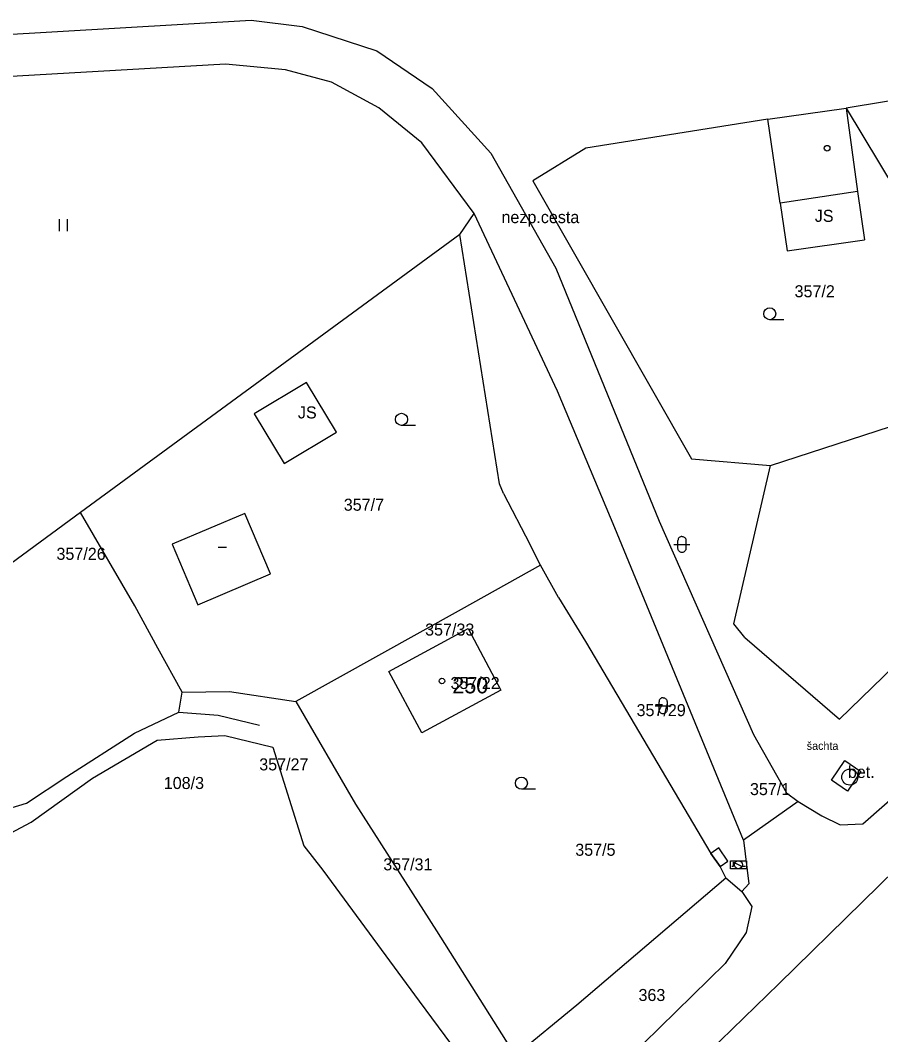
# Model space of a CAD drawing. Extents: x -836739 to -835945, y -1070775 to -1070126.
# Drawn here: x -836511.6 to -836458, y -1070275.3 to -1070212.1 of the extents above; entities that cross this region are included whole.
import ezdxf

# ---------------------------------------------------------------- set-up
doc = ezdxf.new("R2010")
doc.units = 0
for name, color, linetype in [('BodPole_mer', 7, 'Continuous'), ('Budovy_hranice', 7, 'Continuous'), ('Budovy_kody', 7, 'Continuous'), ('Doprava_hranice', 7, 'Continuous'), ('Doprava_kody', 7, 'Continuous'), ('OstPloch_hranice', 7, 'Continuous'), ('OstPloch_kody', 7, 'Continuous'), ('PovrZnIS_body', 7, 'Continuous'), ('PovrZnIS_hranice', 7, 'Continuous'), ('RuianAdr_popis', 7, 'Continuous'), ('RuianPar_popis', 7, 'Continuous'), ('Stavby_hr_stav', 7, 'Continuous'), ('Stavby_kody', 7, 'Continuous'), ('Stavby_linie', 7, 'Continuous'), ('Stavby_popis', 7, 'Continuous'), ('Vodstvo_hranice', 7, 'Continuous')]:
    doc.layers.add(name, color=color, linetype=linetype)

msp = doc.modelspace()

# ---------------------------------------------------------------- linework, layer by layer
at = {"layer": 'BodPole_mer'}
for p, q in [((-836497.22, -1070212.11), (-836497.22, -1070212.11)), ((-836494.05, -1070212.5), (-836494.05, -1070212.5)), ((-836489.39, -1070214.02), (-836489.39, -1070214.02)), ((-836498.82, -1070214.84), (-836498.82, -1070214.84)), ((-836495.08, -1070215.2), (-836495.08, -1070215.2)), ((-836492.22, -1070215.97), (-836492.22, -1070215.97)), ((-836485.93, -1070216.36), (-836485.93, -1070216.36)), ((-836489.27, -1070217.57), (-836489.27, -1070217.57)), ((-836460.13, -1070217.59), (-836460.13, -1070217.59)), ((-836465.02, -1070218.27), (-836465.02, -1070218.27)), ((-836486.58, -1070219.75), (-836486.58, -1070219.75)), ((-836482.28, -1070220.4), (-836482.28, -1070220.4)), ((-836476.36, -1070220.08), (-836476.36, -1070220.08)), ((-836479.66, -1070222.11), (-836479.66, -1070222.11)), ((-836459.42, -1070222.78), (-836459.42, -1070222.78)), ((-836464.25, -1070223.5), (-836464.25, -1070223.5)), ((-836483.33, -1070224.14), (-836483.33, -1070224.14)), ((-836484.22, -1070225.45), (-836484.22, -1070225.45)), ((-836459, -1070225.8), (-836459, -1070225.8)), ((-836463.81, -1070226.48), (-836463.81, -1070226.48)), ((-836478.23, -1070227.56), (-836478.23, -1070227.56)), ((-836493.77, -1070234.68), (-836493.77, -1070234.68)), ((-836478.12, -1070235.21), (-836478.12, -1070235.21)), ((-836497.03, -1070236.63), (-836497.03, -1070236.63)), ((-836491.91, -1070237.78), (-836491.91, -1070237.78)), ((-836469.78, -1070239.43), (-836469.78, -1070239.43)), ((-836495.17, -1070239.73), (-836495.17, -1070239.73)), ((-836464.85, -1070239.86), (-836464.85, -1070239.86)), ((-836481.74, -1070241), (-836481.74, -1070241)), ((-836481.49, -1070241.59), (-836481.49, -1070241.59)), ((-836507.86, -1070242.77), (-836507.86, -1070242.77)), ((-836497.61, -1070242.84), (-836497.61, -1070242.84)), ((-836474.56, -1070243.73), (-836474.56, -1070243.73)), ((-836471.79, -1070243.33), (-836471.79, -1070243.33)), ((-836502.15, -1070244.76), (-836502.15, -1070244.76)), ((-836479.85, -1070244.75), (-836479.85, -1070244.75)), ((-836479.18, -1070246.06), (-836479.18, -1070246.06)), ((-836496.01, -1070246.6), (-836496.01, -1070246.6)), ((-836478.06, -1070248.07), (-836478.06, -1070248.07)), ((-836504.47, -1070248.59), (-836504.47, -1070248.59)), ((-836500.55, -1070248.53), (-836500.55, -1070248.53)), ((-836484.13, -1070248.82), (-836484.13, -1070248.82)), ((-836483.69, -1070250.01), (-836483.69, -1070250.01)), ((-836467.14, -1070249.72), (-836467.14, -1070249.72)), ((-836476.39, -1070250.81), (-836476.39, -1070250.81)), ((-836466.44, -1070250.56), (-836466.44, -1070250.56)), ((-836503.04, -1070251.23), (-836503.04, -1070251.23)), ((-836488.64, -1070252.68), (-836488.64, -1070252.68)), ((-836501.52, -1070253.97), (-836501.52, -1070253.97)), ((-836498.58, -1070253.94), (-836498.58, -1070253.94)), ((-836481.66, -1070253.86), (-836481.66, -1070253.86)), ((-836494.44, -1070254.55), (-836494.44, -1070254.55)), ((-836501.74, -1070255.22), (-836501.74, -1070255.22)), ((-836499.27, -1070255.4), (-836499.27, -1070255.4)), ((-836460.54, -1070255.66), (-836460.54, -1070255.66)), ((-836504.49, -1070256.53), (-836504.49, -1070256.53)), ((-836496.7, -1070256.04), (-836496.7, -1070256.04)), ((-836486.58, -1070256.5), (-836486.58, -1070256.5)), ((-836503.08, -1070256.96), (-836503.08, -1070256.96)), ((-836500.52, -1070256.76), (-836500.52, -1070256.76)), ((-836498.86, -1070256.68), (-836498.86, -1070256.68)), ((-836465.92, -1070256.62), (-836465.92, -1070256.62)), ((-836495.87, -1070257.41), (-836495.87, -1070257.41)), ((-836460.21, -1070258.24), (-836460.21, -1070258.24)), ((-836459.22, -1070258.92), (-836459.22, -1070258.92)), ((-836508.71, -1070259.23), (-836508.71, -1070259.23)), ((-836507.11, -1070259.33), (-836507.11, -1070259.33)), ((-836461.05, -1070259.46), (-836461.05, -1070259.46)), ((-836459.91, -1070259.27), (-836459.91, -1070259.27)), ((-836463.85, -1070260.25), (-836463.85, -1070260.25)), ((-836460.06, -1070260.14), (-836460.06, -1070260.14)), ((-836511.22, -1070260.9), (-836511.22, -1070260.9)), ((-836490.71, -1070260.96), (-836490.71, -1070260.96)), ((-836463.13, -1070260.78), (-836463.13, -1070260.78)), ((-836510.93, -1070262.08), (-836510.93, -1070262.08)), ((-836461.66, -1070261.68), (-836461.66, -1070261.68)), ((-836459.09, -1070262.17), (-836459.09, -1070262.17)), ((-836460.5, -1070262.24), (-836460.5, -1070262.24)), ((-836466.54, -1070263.19), (-836466.54, -1070263.19)), ((-836493.93, -1070263.56), (-836493.93, -1070263.56)), ((-836468.56, -1070264.02), (-836468.56, -1070264.02)), ((-836468.07, -1070263.68), (-836468.07, -1070263.68)), ((-836467.5, -1070264.5), (-836467.5, -1070264.5)), ((-836466.85, -1070264.73), (-836466.85, -1070264.73)), ((-836492.75, -1070265.06), (-836492.75, -1070265.06)), ((-836467.99, -1070264.84), (-836467.99, -1070264.84)), ((-836467.63, -1070265.54), (-836467.63, -1070265.54)), ((-836466.2, -1070265.91), (-836466.2, -1070265.91)), ((-836466.63, -1070266.39), (-836466.63, -1070266.39)), ((-836466.02, -1070267.34), (-836466.02, -1070267.34)), ((-836485.67, -1070268.85), (-836485.67, -1070268.85)), ((-836466.37, -1070268.96), (-836466.37, -1070268.96)), ((-836467.68, -1070270.88), (-836467.68, -1070270.88)), ((-836464.34, -1070272.16), (-836464.34, -1070272.16)), ((-836486.76, -1070273.24), (-836486.76, -1070273.24)), ((-836476.92, -1070273.45), (-836476.92, -1070273.45))]:
    msp.add_line(p, q, dxfattribs=at)
at = {"layer": 'Budovy_hranice'}
for p, q in [((-836497.61, -1070242.84), (-836502.15, -1070244.76)), ((-836496.01, -1070246.6), (-836497.61, -1070242.84)), ((-836502.15, -1070244.76), (-836500.55, -1070248.53)), ((-836500.55, -1070248.53), (-836496.01, -1070246.6))]:
    msp.add_line(p, q, dxfattribs=at)
for points in [[(-836460.13, -1070217.59), (-836459.42, -1070222.78), (-836464.25, -1070223.5), (-836465.02, -1070218.27), (-836460.13, -1070217.59)], [(-836481.66, -1070253.86), (-836486.58, -1070256.5), (-836488.64, -1070252.68), (-836483.69, -1070250.01), (-836481.66, -1070253.86)]]:
    msp.add_lwpolyline(points, dxfattribs=at)
at = {"layer": 'Budovy_kody'}
msp.add_line((-836499.27, -1070244.94), (-836498.77, -1070244.94), dxfattribs=at)
for centre in [(-836461.32, -1070220.08), (-836485.33, -1070253.28)]:
    msp.add_circle(centre, 0.175, dxfattribs=at)
at = {"layer": 'Doprava_hranice'}
for points in [[(-836565.55, -1070255.75), (-836568.29, -1070246.94), (-836565.3, -1070243.45), (-836558.59, -1070239.29), (-836553.32, -1070234.26), (-836550.36, -1070230.73), (-836544.63, -1070222.38), (-836541.42, -1070218.21), (-836539.02, -1070215.95), (-836535.5, -1070213.99), (-836517.48, -1070213.29), (-836497.22, -1070212.11), (-836494.05, -1070212.5), (-836489.39, -1070214.02), (-836485.93, -1070216.36), (-836482.28, -1070220.4), (-836478.23, -1070227.56), (-836471.79, -1070243.33), (-836465.92, -1070256.62), (-836463.85, -1070260.25), (-836463.13, -1070260.78)], [(-836466.54, -1070263.19), (-836474.56, -1070243.73), (-836478.12, -1070235.21), (-836483.33, -1070224.14), (-836486.58, -1070219.75), (-836489.27, -1070217.57), (-836492.22, -1070215.97), (-836495.08, -1070215.2), (-836498.82, -1070214.84), (-836513.64, -1070215.7), (-836532.05, -1070216.8), (-836534.5, -1070217.36), (-836537.57, -1070219.18), (-836540.24, -1070221.43), (-836545, -1070227.8), (-836549.52, -1070233.43), (-836552.32, -1070236.92), (-836557.98, -1070243.27), (-836562.8, -1070249.08), (-836563.01, -1070249.54), (-836561.48, -1070254.69), (-836565.55, -1070255.75)], [(-836463.13, -1070260.78), (-836461.66, -1070261.68), (-836460.5, -1070262.24), (-836459.09, -1070262.17), (-836456.22, -1070259.67), (-836453.89, -1070261.93), (-836464.34, -1070272.16), (-836473.79, -1070281.33)], [(-836463.13, -1070260.78), (-836466.54, -1070263.19), (-836466.2, -1070265.91), (-836466.63, -1070266.39), (-836466.02, -1070267.34), (-836466.37, -1070268.96), (-836467.68, -1070270.88), (-836477.85, -1070280.85), (-836486.39, -1070290.44)]]:
    msp.add_lwpolyline(points, dxfattribs=at)
at = {"layer": 'OstPloch_hranice'}
for p, q in [((-836484.22, -1070225.45), (-836483.33, -1070224.14)), ((-836467.63, -1070265.54), (-836466.63, -1070266.39))]:
    msp.add_line(p, q, dxfattribs=at)
msp.add_lwpolyline([(-836459.22, -1070258.92), (-836460.06, -1070260.14), (-836461.05, -1070259.46), (-836460.21, -1070258.24), (-836459.22, -1070258.92)], dxfattribs=at)
at = {"layer": 'OstPloch_kody'}
for p, q in [((-836509.185, -1070224.51), (-836509.185, -1070225.26)), ((-836508.675, -1070225.26), (-836508.675, -1070224.51)), ((-836464.025, -1070230.77), (-836464.9, -1070230.77)), ((-836486.975, -1070237.35), (-836487.85, -1070237.35)), ((-836470.62, -1070245.02), (-836470.62, -1070244.52)), ((-836470.12, -1070244.52), (-836470.12, -1070245.02)), ((-836470.87, -1070244.77), (-836469.87, -1070244.77)), ((-836471.8, -1070255.07), (-836471.8, -1070254.57)), ((-836471.3, -1070254.57), (-836471.3, -1070255.07)), ((-836472.05, -1070254.82), (-836471.05, -1070254.82)), ((-836479.505, -1070260.02), (-836480.38, -1070260.02))]:
    msp.add_line(p, q, dxfattribs=at)
for points in [[(-836470.37, -1070244.27), (-836470.415, -1070244.274), (-836470.462, -1070244.288), (-836470.507, -1070244.311), (-836470.547, -1070244.343), (-836470.579, -1070244.383), (-836470.602, -1070244.428), (-836470.616, -1070244.475), (-836470.62, -1070244.52)], [(-836470.37, -1070244.27), (-836470.325, -1070244.274), (-836470.278, -1070244.288), (-836470.233, -1070244.311), (-836470.193, -1070244.343), (-836470.161, -1070244.383), (-836470.138, -1070244.428), (-836470.124, -1070244.475), (-836470.12, -1070244.52)], [(-836470.37, -1070245.27), (-836470.415, -1070245.266), (-836470.462, -1070245.252), (-836470.507, -1070245.229), (-836470.547, -1070245.197), (-836470.579, -1070245.157), (-836470.602, -1070245.112), (-836470.616, -1070245.065), (-836470.62, -1070245.02)], [(-836470.12, -1070245.02), (-836470.124, -1070245.065), (-836470.138, -1070245.112), (-836470.161, -1070245.157), (-836470.193, -1070245.197), (-836470.233, -1070245.229), (-836470.278, -1070245.252), (-836470.325, -1070245.266), (-836470.37, -1070245.27)], [(-836471.55, -1070254.32), (-836471.595, -1070254.324), (-836471.642, -1070254.338), (-836471.687, -1070254.361), (-836471.727, -1070254.393), (-836471.759, -1070254.433), (-836471.782, -1070254.478), (-836471.796, -1070254.525), (-836471.8, -1070254.57)], [(-836471.55, -1070254.32), (-836471.505, -1070254.324), (-836471.458, -1070254.338), (-836471.413, -1070254.361), (-836471.373, -1070254.393), (-836471.341, -1070254.433), (-836471.318, -1070254.478), (-836471.304, -1070254.525), (-836471.3, -1070254.57)], [(-836471.55, -1070255.32), (-836471.595, -1070255.316), (-836471.642, -1070255.302), (-836471.687, -1070255.279), (-836471.727, -1070255.247), (-836471.759, -1070255.207), (-836471.782, -1070255.162), (-836471.796, -1070255.115), (-836471.8, -1070255.07)], [(-836471.3, -1070255.07), (-836471.304, -1070255.115), (-836471.318, -1070255.162), (-836471.341, -1070255.207), (-836471.373, -1070255.247), (-836471.413, -1070255.279), (-836471.458, -1070255.302), (-836471.505, -1070255.316), (-836471.55, -1070255.32)]]:
    msp.add_lwpolyline(points, dxfattribs=at)
for centre in [(-836464.9, -1070230.395), (-836487.85, -1070236.975), (-836480.38, -1070259.645)]:
    msp.add_ellipse(centre, major_axis=(0.375, 0), ratio=0.999999, dxfattribs=at)
at = {"layer": 'PovrZnIS_body'}
for p, q in [((-836467.35, -1070264.98), (-836467.35, -1070264.48)), ((-836467.35, -1070264.48), (-836466.35, -1070264.48)), ((-836467.161, -1070264.814), (-836467.161, -1070264.564)), ((-836467.161, -1070264.564), (-836466.661, -1070264.814)), ((-836466.35, -1070264.48), (-836466.35, -1070264.98)), ((-836466.35, -1070264.98), (-836467.35, -1070264.98)), ((-836467.271, -1070264.814), (-836467.161, -1070264.814)), ((-836466.661, -1070264.814), (-836466.416, -1070264.814))]:
    msp.add_line(p, q, dxfattribs=at)
for centre, radius in [((-836459.91, -1070259.27), 0.5), ((-836466.85, -1070264.73), 0.25)]:
    msp.add_circle(centre, radius, dxfattribs=at)
at = {"layer": 'PovrZnIS_hranice'}
msp.add_lwpolyline([(-836467.99, -1070264.84), (-836467.5, -1070264.5), (-836468.07, -1070263.68), (-836468.56, -1070264.02), (-836467.99, -1070264.84)], dxfattribs=at)
at = {"layer": 'RuianAdr_popis'}
msp.add_line((-836484.68, -1070254.05), (-836484.68, -1070254.05), dxfattribs=at)
at = {"layer": 'RuianPar_popis'}
for p, q in [((-836463.35, -1070229.37), (-836463.35, -1070229.37)), ((-836491.45, -1070242.67), (-836491.45, -1070242.67)), ((-836509.36, -1070245.73), (-836509.36, -1070245.73)), ((-836486.38, -1070250.45), (-836486.38, -1070250.45)), ((-836484.8, -1070253.78), (-836484.8, -1070253.78)), ((-836473.2, -1070255.47), (-836473.2, -1070255.47)), ((-836496.72, -1070258.85), (-836496.72, -1070258.85)), ((-836502.67, -1070260.01), (-836502.67, -1070260.01)), ((-836466.13, -1070260.39), (-836466.13, -1070260.39)), ((-836477.02, -1070264.17), (-836477.02, -1070264.17)), ((-836488.99, -1070265.08), (-836488.99, -1070265.08)), ((-836473.08, -1070273.22), (-836473.08, -1070273.22))]:
    msp.add_line(p, q, dxfattribs=at)
at = {"layer": 'Stavby_hr_stav'}
msp.add_line((-836459.42, -1070222.78), (-836459, -1070225.8), dxfattribs=at)
for points in [[(-836464.25, -1070223.5), (-836463.81, -1070226.48), (-836459, -1070225.8)], [(-836493.77, -1070234.68), (-836497.03, -1070236.63), (-836495.17, -1070239.73), (-836491.91, -1070237.78), (-836493.77, -1070234.68)]]:
    msp.add_lwpolyline(points, dxfattribs=at)
at = {"layer": 'Stavby_linie'}
for p, q in [((-836464.85, -1070239.86), (-836449.69, -1070234.92)), ((-836469.78, -1070239.43), (-836464.85, -1070239.86)), ((-836481.49, -1070241.59), (-836479.85, -1070244.75)), ((-836479.18, -1070246.06), (-836484.13, -1070248.82)), ((-836478.06, -1070248.07), (-836476.39, -1070250.81)), ((-836476.39, -1070250.81), (-836468.56, -1070264.02)), ((-836466.44, -1070250.56), (-836460.54, -1070255.66))]:
    msp.add_line(p, q, dxfattribs=at)
for points in [[(-836439.81, -1070215.21), (-836443.91, -1070214.91), (-836460.13, -1070217.59), (-836449.69, -1070234.92)], [(-836465.02, -1070218.27), (-836476.36, -1070220.08), (-836479.66, -1070222.11), (-836469.78, -1070239.43)], [(-836481.49, -1070241.59), (-836481.74, -1070241), (-836484.22, -1070225.45), (-836507.86, -1070242.77), (-836514.01, -1070247.28)], [(-836460.54, -1070255.66), (-836450.32, -1070245.76), (-836439.91, -1070235.75)], [(-836466.44, -1070250.56), (-836467.14, -1070249.72), (-836464.85, -1070239.86)], [(-836501.52, -1070253.97), (-836503.04, -1070251.23), (-836504.47, -1070248.59), (-836507.86, -1070242.77)], [(-836478.06, -1070248.07), (-836479.18, -1070246.06), (-836479.85, -1070244.75)], [(-836484.13, -1070248.82), (-836494.44, -1070254.55), (-836490.71, -1070260.96)], [(-836508.71, -1070259.23), (-836504.49, -1070256.53), (-836501.74, -1070255.22), (-836501.52, -1070253.97), (-836498.58, -1070253.94), (-836494.44, -1070254.55)], [(-836501.74, -1070255.22), (-836499.27, -1070255.4), (-836496.7, -1070256.04)], [(-836529.71, -1070265.69), (-836519.75, -1070263.47), (-836511.22, -1070260.9), (-836508.71, -1070259.23)], [(-836490.71, -1070260.96), (-836485.67, -1070268.85), (-836480.77, -1070276.62), (-836476.92, -1070273.45)], [(-836476.92, -1070273.45), (-836467.63, -1070265.54), (-836467.99, -1070264.84), (-836468.56, -1070264.02)]]:
    msp.add_lwpolyline(points, dxfattribs=at)
at = {"layer": 'Vodstvo_hranice'}
msp.add_lwpolyline([(-836529.5, -1070277.24), (-836526.44, -1070274.72), (-836525.34, -1070271.43), (-836521.88, -1070269.71), (-836516.37, -1070264.96), (-836510.93, -1070262.08), (-836507.11, -1070259.33), (-836503.08, -1070256.96), (-836500.52, -1070256.76), (-836498.86, -1070256.68), (-836495.87, -1070257.41), (-836493.93, -1070263.56), (-836492.75, -1070265.06), (-836486.76, -1070273.24), (-836482.01, -1070279.63)], dxfattribs=at)

# ---------------------------------------------------------------- texts
at = {"layer": 'Doprava_kody'}
msp.add_text('nezp.cesta', height=0.75, dxfattribs=at).set_placement((-836481.62, -1070224.75))
at = {"layer": 'RuianAdr_popis'}
msp.add_text('250', height=1, dxfattribs=at).set_placement((-836484.68, -1070254.05))
at = {"layer": 'RuianPar_popis'}
for s, p in [('357/2', (-836463.35, -1070229.37)), ('357/7', (-836491.45, -1070242.67)), ('357/26', (-836509.36, -1070245.73)), ('357/33', (-836486.38, -1070250.45)), ('357/22', (-836484.8, -1070253.78)), ('357/29', (-836473.2, -1070255.47)), ('357/27', (-836496.72, -1070258.85)), ('108/3', (-836502.67, -1070260.01)), ('357/1', (-836466.13, -1070260.39)), ('357/5', (-836477.02, -1070264.17)), ('357/31', (-836488.99, -1070265.08)), ('363', (-836473.08, -1070273.22))]:
    msp.add_text(s, height=0.75, dxfattribs=at).set_placement(p)
at = {"layer": 'Stavby_kody'}
for s, p in [('JS', (-836462.09, -1070224.67)), ('JS', (-836494.31, -1070236.92)), ('bet.', (-836460.03, -1070259.32))]:
    msp.add_text(s, height=0.75, dxfattribs=at).set_placement(p)
at = {"layer": 'Stavby_popis'}
msp.add_text('šachta', height=0.5, dxfattribs=at).set_placement((-836462.59, -1070257.57))

doc.saveas('drawing.dxf')
